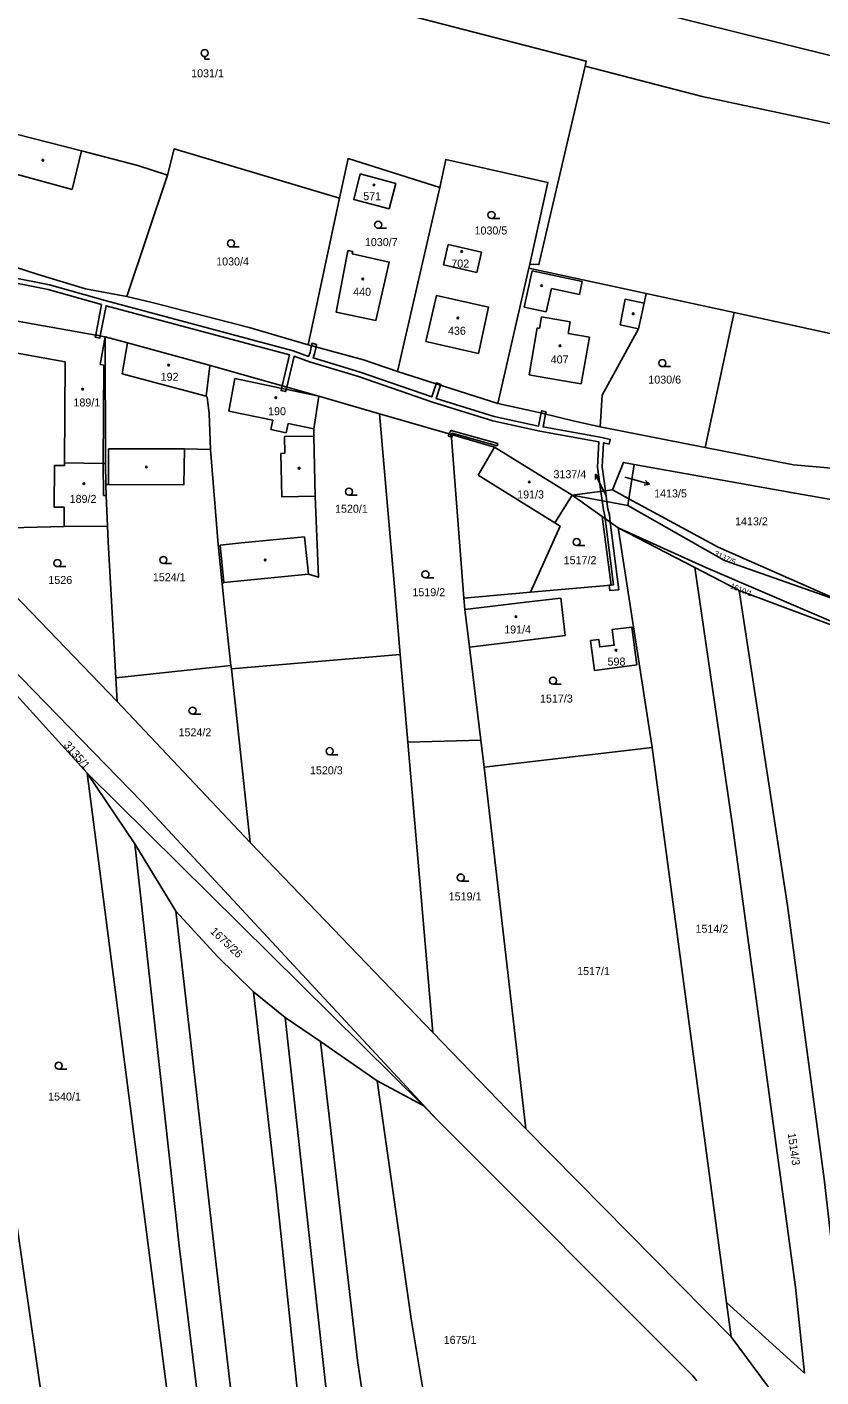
# Model space of a CAD drawing. Extents: x -776734 to -748832, y -1118122 to -976986.
# Drawn here: x -752749.1 to -752580.4, y -1115951.8 to -1115665 of the extents above; entities that cross this region are included whole.
import ezdxf

# ---------------------------------------------------------------- set-up
doc = ezdxf.new("R2010")
doc.units = 0
for name, color, linetype in [('KM_Hranice parcel', 7, 'Continuous'), ('KM_Parcelní čísla', 7, 'Continuous'), ('KM_Pop  PČ popisy', 7, 'Continuous'), ('KM_Vnitřní kresba', 7, 'Continuous'), ('KM_Věcná břemena k části', 7, 'Continuous'), ('KM_Značky budov', 7, 'Continuous'), ('KM_Značky kultur', 7, 'Continuous')]:
    doc.layers.add(name, color=color, linetype=linetype)

msp = doc.modelspace()

# ---------------------------------------------------------------- linework, layer by layer
at = {"layer": 'KM_Hranice parcel'}
for p, q in [((-752727.86, -1115722.24), (-752719.2, -1115696.43)), ((-752661.38, -1115699.08), (-752670.35, -1115738.18)), ((-752689.33, -1115732.46), (-752682.68, -1115701.34)), ((-752642.51, -1115716.16), (-752649.1, -1115744.92)), ((-752642.51, -1115716.16), (-752642.29, -1115715.33)), ((-752642.51, -1115716.16), (-752617.57, -1115721.57)), ((-752598.87, -1115725.63), (-752617.57, -1115721.57)), ((-752521.98, -1115742.33), (-752598.87, -1115725.63)), ((-752732.4, -1115757.7), (-752732.48, -1115730.75)), ((-752687.12, -1115743.37), (-752710.36, -1115736.79)), ((-752670.35, -1115738.18), (-752649.1, -1115744.92)), ((-752674.22, -1115747.13), (-752687.12, -1115743.37)), ((-752627.35, -1115749.91), (-752626.89, -1115743.19)), ((-752674.22, -1115747.13), (-752671.03, -1115783.91)), ((-752658.67, -1115751.61), (-752674.22, -1115747.13)), ((-752627.35, -1115749.91), (-752605.01, -1115754.28)), ((-752732.3, -1115762.17), (-752732.4, -1115757.7)), ((-752620.09, -1115757.87), (-752621.23, -1115765.2)), ((-752633.26, -1115764.42), (-752624.74, -1115763.31)), ((-752624.74, -1115763.31), (-752621.23, -1115765.2)), ((-752626.91, -1115768.92), (-752633.26, -1115764.42)), ((-752621.45, -1115766.58), (-752633.26, -1115764.42)), ((-752621.45, -1115766.58), (-752621.23, -1115765.2)), ((-752741.18, -1115771.07), (-752741.17, -1115766.99)), ((-752623.48, -1115771.34), (-752626.91, -1115768.92)), ((-752762.62, -1115771.65), (-752741.18, -1115771.07)), ((-752741.18, -1115771.07), (-752731.98, -1115771)), ((-752616.32, -1115818.03), (-752623.48, -1115771.34)), ((-752623.48, -1115771.34), (-752607.2, -1115779.76)), ((-752729.95, -1115808.28), (-752762.79, -1115774.11)), ((-752607.2, -1115779.76), (-752597.82, -1115784.65)), ((-752707.63, -1115783.27), (-752707.1, -1115788.16)), ((-752671.03, -1115783.91), (-752669.79, -1115798.26)), ((-752656.29, -1115786.27), (-752642.16, -1115785.02)), ((-752656.29, -1115786.27), (-752656.1, -1115788.71)), ((-752634.73, -1115794.21), (-752635.68, -1115786.27)), ((-752597.82, -1115784.65), (-752569.92, -1115795.14)), ((-752707.1, -1115788.16), (-752705.75, -1115800.64)), ((-752656.1, -1115788.71), (-752655.07, -1115796.74)), ((-752705.67, -1115801.34), (-752669.79, -1115798.26)), ((-752669.79, -1115798.26), (-752668.18, -1115816.87)), ((-752655.07, -1115796.74), (-752652.69, -1115816.5)), ((-752730.23, -1115803.24), (-752705.75, -1115800.64)), ((-752705.75, -1115800.64), (-752705.67, -1115801.34)), ((-752730.23, -1115803.24), (-752729.95, -1115808.28)), ((-752701.69, -1115838.24), (-752705.67, -1115801.34)), ((-752701.69, -1115838.24), (-752729.95, -1115808.28)), ((-752652.69, -1115816.5), (-752668.18, -1115816.87)), ((-752668.18, -1115816.87), (-752662.84, -1115878.54)), ((-752652.69, -1115816.5), (-752652, -1115822.21)), ((-752616.32, -1115818.03), (-752652, -1115822.21)), ((-752600.49, -1115935.92), (-752616.32, -1115818.03)), ((-752736.32, -1115823.45), (-752664.94, -1115894.11)), ((-752726.15, -1115838.5), (-752736.32, -1115823.45)), ((-752736.32, -1115823.45), (-752718.32, -1115962.58)), ((-752652, -1115822.21), (-752643.1, -1115899.02)), ((-752662.84, -1115878.54), (-752701.69, -1115838.24)), ((-752744.62, -1115965.33), (-752762.91, -1115838.6)), ((-752717.46, -1115852.77), (-752726.15, -1115838.5)), ((-752700.98, -1115869.92), (-752694.25, -1115875.41)), ((-752694.25, -1115875.41), (-752686.73, -1115880.48)), ((-752643.1, -1115899.02), (-752662.84, -1115878.54)), ((-752674.7, -1115888.81), (-752686.73, -1115880.48)), ((-752664.94, -1115894.11), (-752674.7, -1115888.81)), ((-752664.94, -1115894.11), (-752661.99, -1115897.03)), ((-752599.51, -1115943.24), (-752643.1, -1115899.02)), ((-752599.51, -1115943.24), (-752600.49, -1115935.92))]:
    msp.add_line(p, q, dxfattribs=at)
for points in [[(-752333.04, -1115729.69), (-752351.84, -1115723.27), (-752408.77, -1115709.73), (-752459.96, -1115696.52), (-752489.72, -1115689.72), (-752538.31, -1115679.58), (-752557.93, -1115676.12), (-752626.99, -1115658.88), (-752700.73, -1115640.21), (-752719.19, -1115635.5)], [(-752630.53, -1115673.3), (-752630.28, -1115672.22), (-752697.23, -1115654.9)], [(-752630.53, -1115673.3), (-752636.38, -1115698.42), (-752640.34, -1115715.42), (-752642.29, -1115715.33)], [(-752630.53, -1115673.3), (-752605.68, -1115679.71), (-752561.98, -1115689.03)], [(-752719.2, -1115696.43), (-752725.51, -1115694.41), (-752737.47, -1115691.3), (-752751.34, -1115687.73), (-752760.01, -1115685.71), (-752762.66, -1115685.09), (-752769.92, -1115683.54)], [(-752682.68, -1115701.34), (-752717.8, -1115690.85), (-752719.2, -1115696.43)], [(-752661.38, -1115699.08), (-752680.88, -1115692.93), (-752682.68, -1115701.34)], [(-752642.29, -1115715.33), (-752638.44, -1115697.96), (-752660.14, -1115693.08), (-752661.38, -1115699.08)], [(-752672.15, -1115703.58), (-752679.67, -1115701.62), (-752678.28, -1115696.17), (-752670.76, -1115698.23), (-752672.15, -1115703.58)], [(-752768.29, -1115711.67), (-752767.84, -1115711.76), (-752758.58, -1115713.72), (-752746.7, -1115717.52), (-752736.61, -1115720.55), (-752727.86, -1115722.24)], [(-752659.63, -1115711.19), (-752652.57, -1115712.79), (-752653.55, -1115717.08), (-752660.6, -1115715.5), (-752659.63, -1115711.19)], [(-752680.86, -1115712.41), (-752680.97, -1115712.9), (-752683.4, -1115725.55), (-752674.96, -1115727.31), (-752672.14, -1115714.91), (-752679.99, -1115713.12), (-752679.87, -1115712.64), (-752680.86, -1115712.41)], [(-752727.86, -1115722.24), (-752722.5, -1115723.52), (-752701.9, -1115728.78), (-752689.33, -1115732.46)], [(-752664.33, -1115731.77), (-752653.2, -1115734.31), (-752651.03, -1115724.47), (-752662.1, -1115722.01), (-752664.33, -1115731.77)], [(-752626.89, -1115743.19), (-752619.18, -1115729.06), (-752618.02, -1115723.64), (-752617.57, -1115721.57)], [(-752732.48, -1115730.75), (-752755.56, -1115726.65), (-752761.29, -1115725.71)], [(-752598.87, -1115725.63), (-752599.08, -1115726.57), (-752605.01, -1115754.28)], [(-752710.36, -1115736.79), (-752727.73, -1115732.05), (-752732.48, -1115730.75)], [(-752689.33, -1115732.46), (-752677.57, -1115735.69), (-752670.35, -1115738.18)], [(-752710.36, -1115736.79), (-752710.25, -1115736.97), (-752711.04, -1115743.38), (-752710.78, -1115743.58), (-752710.36, -1115747.06), (-752710.09, -1115754.7)], [(-752707.63, -1115783.27), (-752707.28, -1115782.94), (-752689.3, -1115781.2), (-752687.16, -1115781.86), (-752687.85, -1115764.66), (-752688.13, -1115751.85), (-752688.16, -1115750.3), (-752687.12, -1115743.37)], [(-752649.1, -1115744.92), (-752642.88, -1115746.27), (-752639.73, -1115747), (-752632.81, -1115748.67), (-752627.35, -1115749.91)], [(-752658.67, -1115751.61), (-752658.91, -1115752.24), (-752656.29, -1115786.27)], [(-752633.26, -1115764.42), (-752649.76, -1115754.25), (-752658.67, -1115751.61)], [(-752732.3, -1115762.17), (-752731.78, -1115762.17), (-752715.75, -1115762.2), (-752715.64, -1115754.61), (-752710.09, -1115754.7)], [(-752710.09, -1115754.7), (-752708.46, -1115774.93), (-752707.63, -1115783.27)], [(-752605.01, -1115754.28), (-752586.3, -1115757.95), (-752577.41, -1115758.77), (-752572.97, -1115758.97)], [(-752741.17, -1115766.99), (-752743.27, -1115766.98), (-752743.21, -1115758.1), (-752741.11, -1115758.12), (-752741.1, -1115757.52), (-752732.9, -1115757.69), (-752732.4, -1115757.7)], [(-752624.74, -1115763.31), (-752622.38, -1115757.46), (-752620.09, -1115757.87)], [(-752572.27, -1115766.41), (-752586.78, -1115763.87), (-752620.09, -1115757.87)], [(-752731.98, -1115771), (-752732.28, -1115764.49), (-752732.3, -1115762.17)], [(-752642.16, -1115785.02), (-752635.84, -1115771), (-752636.93, -1115770.31), (-752633.26, -1115764.42)], [(-752575.95, -1115787.1), (-752600.95, -1115778.27), (-752621.45, -1115766.58)], [(-752621.23, -1115765.2), (-752602.24, -1115775.46), (-752575.95, -1115787.1)], [(-752642.16, -1115785.02), (-752625.01, -1115783.51), (-752626.91, -1115768.92)], [(-752731.98, -1115771), (-752731.82, -1115774.35), (-752730.23, -1115803.24)], [(-752623.48, -1115771.34), (-752604.89, -1115779.8), (-752572.75, -1115793.56), (-752569.92, -1115795.14)], [(-752736.32, -1115823.45), (-752750.53, -1115807.77), (-752767.96, -1115789.02), (-752775.93, -1115776.97)], [(-752775.93, -1115776.97), (-752724.69, -1115829.55), (-752661.99, -1115897.03)], [(-752600.49, -1115935.92), (-752583.95, -1115950.94), (-752585.81, -1115932.71), (-752599.21, -1115834.59), (-752607.2, -1115779.76)], [(-752635.68, -1115786.27), (-752643.13, -1115787.17), (-752656.1, -1115788.71)], [(-752597.82, -1115784.65), (-752587.55, -1115851.61), (-752579.78, -1115909.63), (-752576.33, -1115939.32), (-752568.82, -1115995.34)], [(-752623.71, -1115801.01), (-752619.56, -1115800.48), (-752620.58, -1115792.43), (-752624.79, -1115792.97), (-752624.34, -1115796.29), (-752627.42, -1115796.67), (-752627.62, -1115795.08), (-752629.35, -1115795.31), (-752628.53, -1115801.64), (-752623.71, -1115801.01)], [(-752655.07, -1115796.74), (-752642.18, -1115795.17), (-752634.73, -1115794.21)], [(-752662.19, -1116282.11), (-752668.01, -1116248.64), (-752677.71, -1116178.28), (-752684.44, -1116131.42), (-752690.66, -1116092.35), (-752699.96, -1116036.37), (-752706.41, -1115997.92), (-752707.04, -1115993.55), (-752711.91, -1115963.12), (-752716.72, -1115923.92), (-752726.15, -1115838.5)], [(-752700.98, -1115869.92), (-752708.63, -1115862.43), (-752717.46, -1115852.77)], [(-752655.85, -1116280.04), (-752671.21, -1116179.91), (-752676.02, -1116137.58), (-752683.52, -1116085.4), (-752689.47, -1116054.76), (-752699.17, -1115994.89), (-752704.99, -1115961.35), (-752709.62, -1115921.76), (-752717.46, -1115852.77)], [(-752688.65, -1115991.74), (-752685.98, -1115990.94), (-752691.18, -1115959.01), (-752696.12, -1115911.77), (-752700.98, -1115869.92)], [(-752637.24, -1116274.26), (-752645, -1116222.85), (-752654.25, -1116155.12), (-752660.88, -1116105.13), (-752679.05, -1115991.31), (-752679.44, -1115988.99), (-752685.37, -1115955.79), (-752694.25, -1115875.41)], [(-752686.73, -1115880.48), (-752678.9, -1115948.29), (-752672.97, -1115987.58), (-752671.94, -1115995), (-752661.87, -1116061.89), (-752657.06, -1116089.41), (-752646.13, -1116165.35), (-752638.97, -1116217.3), (-752630.75, -1116272.9)], [(-752674.7, -1115888.81), (-752667.44, -1115939.43), (-752658.99, -1115990.41)], [(-752606.8, -1115952.58), (-752607.65, -1115951.53), (-752661.99, -1115897.03)], [(-752599.51, -1115943.24), (-752583.63, -1115964.63), (-752568.82, -1115995.34)]]:
    msp.add_lwpolyline(points, dxfattribs=at)
at = {"layer": 'KM_Pop  PČ popisy'}
for p, q in [((-752628.336, -1115759.963), (-752628.347, -1115761.082)), ((-752627.02, -1115762.66), (-752628.336, -1115759.963)), ((-752628.336, -1115759.963), (-752627.446, -1115760.643)), ((-752622.09, -1115760.57), (-752619.75, -1115761.23)), ((-752626.02, -1115764.66), (-752627.02, -1115762.66)), ((-752619.75, -1115761.23), (-752616.865, -1115762.057)), ((-752616.865, -1115762.057), (-752617.966, -1115762.262)), ((-752616.865, -1115762.057), (-752617.69, -1115761.3))]:
    msp.add_line(p, q, dxfattribs=at)
at = {"layer": 'KM_Vnitřní kresba'}
for p, q in [((-752739.48, -1115699.47), (-752737.47, -1115691.3)), ((-752753.39, -1115695.67), (-752739.48, -1115699.47)), ((-752643.47, -1115724.45), (-752641.8, -1115716.78)), ((-752641.8, -1115716.78), (-752631.12, -1115719.06)), ((-752637.67, -1115720.49), (-752638.83, -1115725.46)), ((-752631.74, -1115721.82), (-752637.67, -1115720.49)), ((-752631.12, -1115719.06), (-752631.74, -1115721.82)), ((-752622.01, -1115722.77), (-752623.08, -1115728.2)), ((-752618.02, -1115723.64), (-752622.01, -1115722.77)), ((-752638.83, -1115725.46), (-752643.47, -1115724.45)), ((-752639.82, -1115726.51), (-752640.25, -1115728.98)), ((-752633.7, -1115727.59), (-752639.82, -1115726.51)), ((-752640.69, -1115728.9), (-752642.38, -1115738.86)), ((-752640.25, -1115728.98), (-752640.69, -1115728.9)), ((-752634.14, -1115730.05), (-752633.7, -1115727.59)), ((-752623.08, -1115728.2), (-752619.18, -1115729.06)), ((-752733.5, -1115736.69), (-752732.48, -1115730.75)), ((-752727.73, -1115732.05), (-752728.83, -1115738.67)), ((-752629.6, -1115730.85), (-752634.14, -1115730.05)), ((-752631.37, -1115740.8), (-752629.6, -1115730.85)), ((-752740.98, -1115736.06), (-752756.83, -1115733.24)), ((-752741.1, -1115757.52), (-752740.98, -1115736.06)), ((-752732.77, -1115736.8), (-752733.5, -1115736.69)), ((-752732.77, -1115736.8), (-752732.9, -1115757.69)), ((-752728.83, -1115738.67), (-752711.04, -1115743.38)), ((-752704.91, -1115739.65), (-752706.22, -1115746.55)), ((-752687.12, -1115743.37), (-752704.91, -1115739.65)), ((-752642.38, -1115738.86), (-752641.69, -1115738.98)), ((-752641.69, -1115738.98), (-752638.45, -1115739.55)), ((-752638.45, -1115739.55), (-752632.25, -1115740.66)), ((-752632.25, -1115740.66), (-752631.37, -1115740.8)), ((-752706.22, -1115746.55), (-752696.86, -1115748.5)), ((-752696.86, -1115748.5), (-752697.28, -1115750.49)), ((-752694.03, -1115751.17), (-752693.62, -1115749.17)), ((-752693.62, -1115749.17), (-752688.16, -1115750.3)), ((-752697.28, -1115750.49), (-752694.03, -1115751.17)), ((-752694.38, -1115751.99), (-752688.13, -1115751.85)), ((-752694.28, -1115755.52), (-752694.38, -1115751.99)), ((-752731.75, -1115754.56), (-752731.78, -1115762.17)), ((-752715.64, -1115754.61), (-752731.75, -1115754.56)), ((-752649.76, -1115754.25), (-752653.24, -1115760.19)), ((-752732.8, -1115764.51), (-752732.9, -1115757.69)), ((-752695.18, -1115755.54), (-752694.28, -1115755.52)), ((-752694.97, -1115764.78), (-752695.18, -1115755.54)), ((-752653.24, -1115760.19), (-752636.93, -1115770.31)), ((-752732.28, -1115764.49), (-752732.8, -1115764.51)), ((-752687.85, -1115764.66), (-752694.97, -1115764.78)), ((-752703.49, -1115774.58), (-752708.07, -1115775.02)), ((-752708.07, -1115775.02), (-752707.28, -1115782.94)), ((-752690.13, -1115773.29), (-752703.49, -1115774.58)), ((-752689.3, -1115781.2), (-752690.13, -1115773.29))]:
    msp.add_line(p, q, dxfattribs=at)
at = {"layer": 'KM_Věcná břemena k části'}
msp.add_lwpolyline([(-752761.3, -1115717.4), (-752744.56, -1115720.72), (-752733.26, -1115723.91), (-752734.48, -1115730.39), (-752733.5, -1115730.57), (-752732.29, -1115724.18), (-752693.29, -1115734.63), (-752694.87, -1115741.18), (-752693.91, -1115741.45), (-752692.34, -1115734.92), (-752689.08, -1115736.07), (-752678.68, -1115739.24), (-752662.95, -1115744.66), (-752650.1, -1115748.66), (-752640.17, -1115750.82), (-752627.6, -1115753.1), (-752627.93, -1115758.46), (-752627.2, -1115763.63), (-752626.92, -1115765.58), (-752626.65, -1115767.51), (-752626.36, -1115768.81), (-752626.29, -1115769.36), (-752625.19, -1115770.13), (-752625.38, -1115768.63), (-752625.67, -1115767.32), (-752625.89, -1115765.77), (-752626.21, -1115763.5), (-752626.93, -1115758.42), (-752626.61, -1115753.3), (-752625.41, -1115753.56), (-752625.2, -1115752.59), (-752627, -1115752.19), (-752639.47, -1115749.93), (-752638.91, -1115747.2), (-752639.88, -1115746.96), (-752640.46, -1115749.73), (-752649.86, -1115747.69), (-752662.17, -1115743.86), (-752661.23, -1115741.07), (-752662.17, -1115740.77), (-752663.12, -1115743.55), (-752678.34, -1115738.3), (-752688.3, -1115735.27), (-752687.99, -1115734.39), (-752687.66, -1115732.92), (-752688.63, -1115732.65), (-752688.95, -1115734.1), (-752689.26, -1115734.96), (-752692.55, -1115733.79), (-752732.5, -1115723.08), (-752744.32, -1115719.75), (-752761.17, -1115716.41)], dxfattribs=at)
for points in [[(-752733.5, -1115730.57), (-752734.48, -1115730.39), (-752734.57, -1115730.88), (-752733.59, -1115731.06)], [(-752688.63, -1115732.65), (-752687.66, -1115732.92), (-752687.55, -1115732.43), (-752688.52, -1115732.16)], [(-752662.17, -1115740.77), (-752661.23, -1115741.07), (-752661.17, -1115740.91), (-752662.11, -1115740.59)], [(-752693.91, -1115741.45), (-752694.87, -1115741.18), (-752695.12, -1115742.21), (-752694.14, -1115742.42)], [(-752639.88, -1115746.96), (-752638.91, -1115747.2), (-752638.81, -1115746.71), (-752639.78, -1115746.47)], [(-752659.58, -1115751.87), (-752659.1, -1115752.01), (-752658.96, -1115751.53), (-752659.44, -1115751.39)], [(-752649.22, -1115753.94), (-752649.08, -1115753.45), (-752658.97, -1115750.67), (-752659.44, -1115751.39), (-752658.96, -1115751.53), (-752658.77, -1115751.25)], [(-752624.51, -1115783.47), (-752625.01, -1115783.51), (-752625.4, -1115783.54), (-752625.31, -1115784.66), (-752623.37, -1115784.51), (-752625.19, -1115770.13), (-752626.29, -1115769.36)]]:
    msp.add_lwpolyline(points, close=True, dxfattribs=at)
at = {"layer": 'KM_Značky budov'}
for centre in [(-752745.7068, -1115693.2592), (-752675.3668, -1115698.5292), (-752656.7468, -1115712.6592), (-752677.7468, -1115718.4992), (-752639.7568, -1115719.9092), (-752620.3168, -1115725.8892), (-752657.5468, -1115726.7892), (-752635.8668, -1115732.6892), (-752718.9768, -1115736.7892), (-752737.2368, -1115741.8992), (-752696.2068, -1115743.7092), (-752723.7068, -1115758.4192), (-752691.2768, -1115758.6992), (-752736.9868, -1115761.9692), (-752642.3868, -1115761.6192), (-752698.4668, -1115778.1992), (-752645.2068, -1115790.2492), (-752623.9768, -1115797.3592)]:
    msp.add_circle(centre, 0.175, dxfattribs=at)
at = {"layer": 'KM_Značky kultur'}
for p, q in [((-752711.32, -1115671.262), (-752711.32, -1115671.76)), ((-752711.32, -1115671.76), (-752710.319, -1115671.76)), ((-752650.413, -1115705.64), (-752648.663, -1115705.64)), ((-752674.483, -1115707.73), (-752672.733, -1115707.73)), ((-752705.743, -1115711.69), (-752703.993, -1115711.69)), ((-752614.113, -1115737.11), (-752612.363, -1115737.11)), ((-752680.683, -1115764.42), (-752678.933, -1115764.42)), ((-752632.333, -1115775.13), (-752630.583, -1115775.13)), ((-752742.603, -1115779.6), (-752740.853, -1115779.6)), ((-752720.103, -1115778.93), (-752718.353, -1115778.93)), ((-752664.443, -1115781.98), (-752662.693, -1115781.98)), ((-752637.353, -1115804.57), (-752635.603, -1115804.57)), ((-752713.913, -1115810.94), (-752712.163, -1115810.94)), ((-752684.783, -1115819.56), (-752683.033, -1115819.56)), ((-752656.943, -1115846.41), (-752655.193, -1115846.41)), ((-752742.333, -1115886.37), (-752740.583, -1115886.37))]:
    msp.add_line(p, q, dxfattribs=at)
for centre in [(-752711.3193, -1115670.5109), (-752674.4829, -1115706.9798), (-752650.4129, -1115704.8898), (-752705.7429, -1115710.9398), (-752614.1129, -1115736.3598), (-752680.6829, -1115763.6698), (-752632.3329, -1115774.3798), (-752742.6029, -1115778.8498), (-752720.1029, -1115778.1798), (-752664.4429, -1115781.2298), (-752637.3529, -1115803.8198), (-752713.9129, -1115810.1898), (-752684.7829, -1115818.8098), (-752656.9429, -1115845.6598), (-752742.3329, -1115885.6198)]:
    msp.add_circle(centre, 0.75, dxfattribs=at)

# ---------------------------------------------------------------- texts
at = {"layer": 'KM_Parcelní čísla'}
for s, p in [('1031/1', (-752714.2, -1115675.64)), ('571', (-752677.655, -1115701.75)), ('1030/5', (-752654.017, -1115709.04)), ('1030/7', (-752677.3, -1115711.5)), ('1030/4', (-752708.89, -1115715.62)), ('702', (-752658.945, -1115716.06)), ('440', (-752679.79, -1115722.07)), ('436', (-752659.65, -1115730.35)), ('407', (-752637.84, -1115736.44)), ('192', (-752720.68, -1115740.12)), ('1030/6', (-752617.1, -1115740.72)), ('189/1', (-752739.2, -1115745.58)), ('190', (-752697.86, -1115747.43)), ('3137/4', (-752637.245, -1115760.82)), ('191/3', (-752644.96, -1115765.12)), ('1413/5', (-752615.86, -1115764.898)), ('189/2', (-752740.01, -1115766.06)), ('1520/1', (-752683.64, -1115768.15)), ('1413/2', (-752598.67, -1115770.83)), ('1517/2', (-752635.08, -1115779.08)), ('1524/1', (-752722.34, -1115782.7)), ('1526', (-752744.53, -1115783.28)), ('1519/2', (-752667.21, -1115785.89)), ('191/4', (-752647.71, -1115793.8)), ('598', (-752625.76, -1115800.62)), ('1517/3', (-752640.11, -1115808.48)), ('1524/2', (-752716.88, -1115815.66)), ('1520/3', (-752688.967, -1115823.73)), ('1519/1', (-752659.49, -1115850.51)), ('1514/2', (-752607.08, -1115857.38)), ('1517/1', (-752632.22, -1115866.37)), ('1540/1', (-752744.58, -1115893.03)), ('1675/1', (-752660.56, -1115944.72))]:
    msp.add_text(s, height=1.7, dxfattribs=at).set_placement(p)
for s, height, rotation, p in [('3137/5', 1.14, 335, (-752603.23, -1115777.197)), ('1510/1', 1.14, 338, (-752599.818, -1115784.126)), ('3135/1', 1.7, 311, (-752741.381, -1115817.577)), ('1675/26', 1.7, 317, (-752710.269, -1115857.271)), ('1514/3', 1.7, 278, (-752587.501, -1115900.018))]:
    msp.add_text(s, height=height, rotation=rotation, dxfattribs=at).set_placement(p)

doc.saveas('drawing.dxf')
